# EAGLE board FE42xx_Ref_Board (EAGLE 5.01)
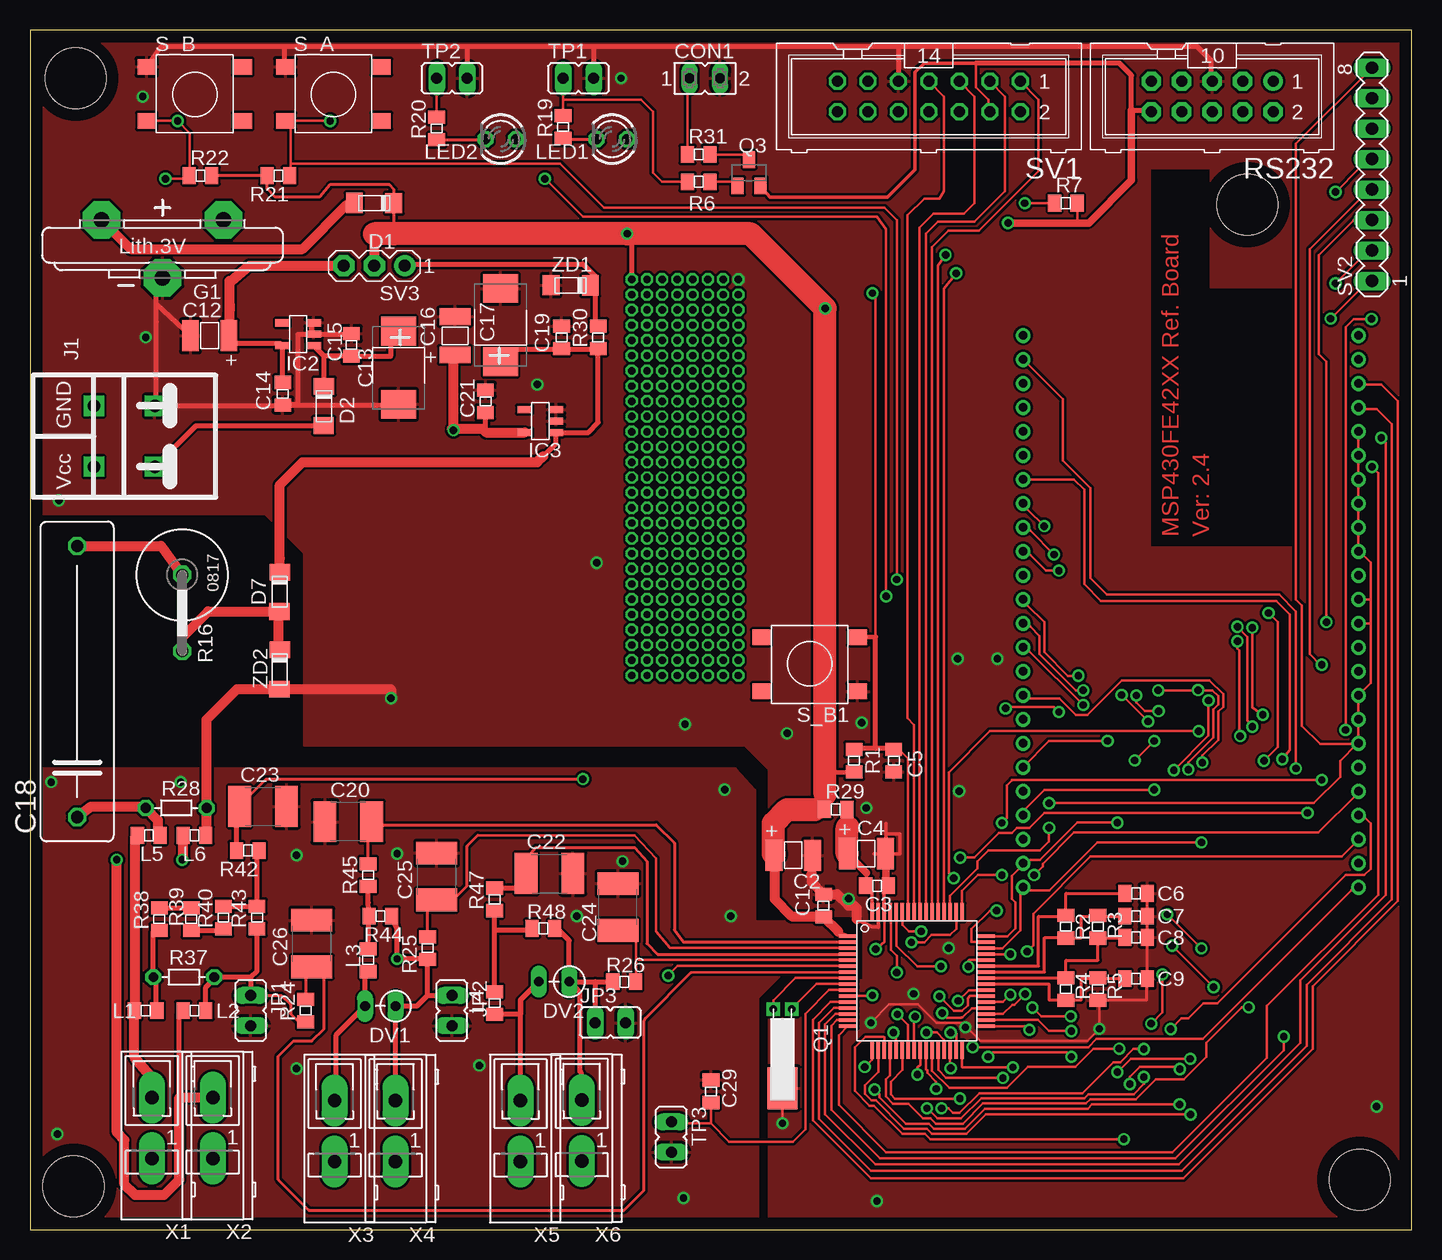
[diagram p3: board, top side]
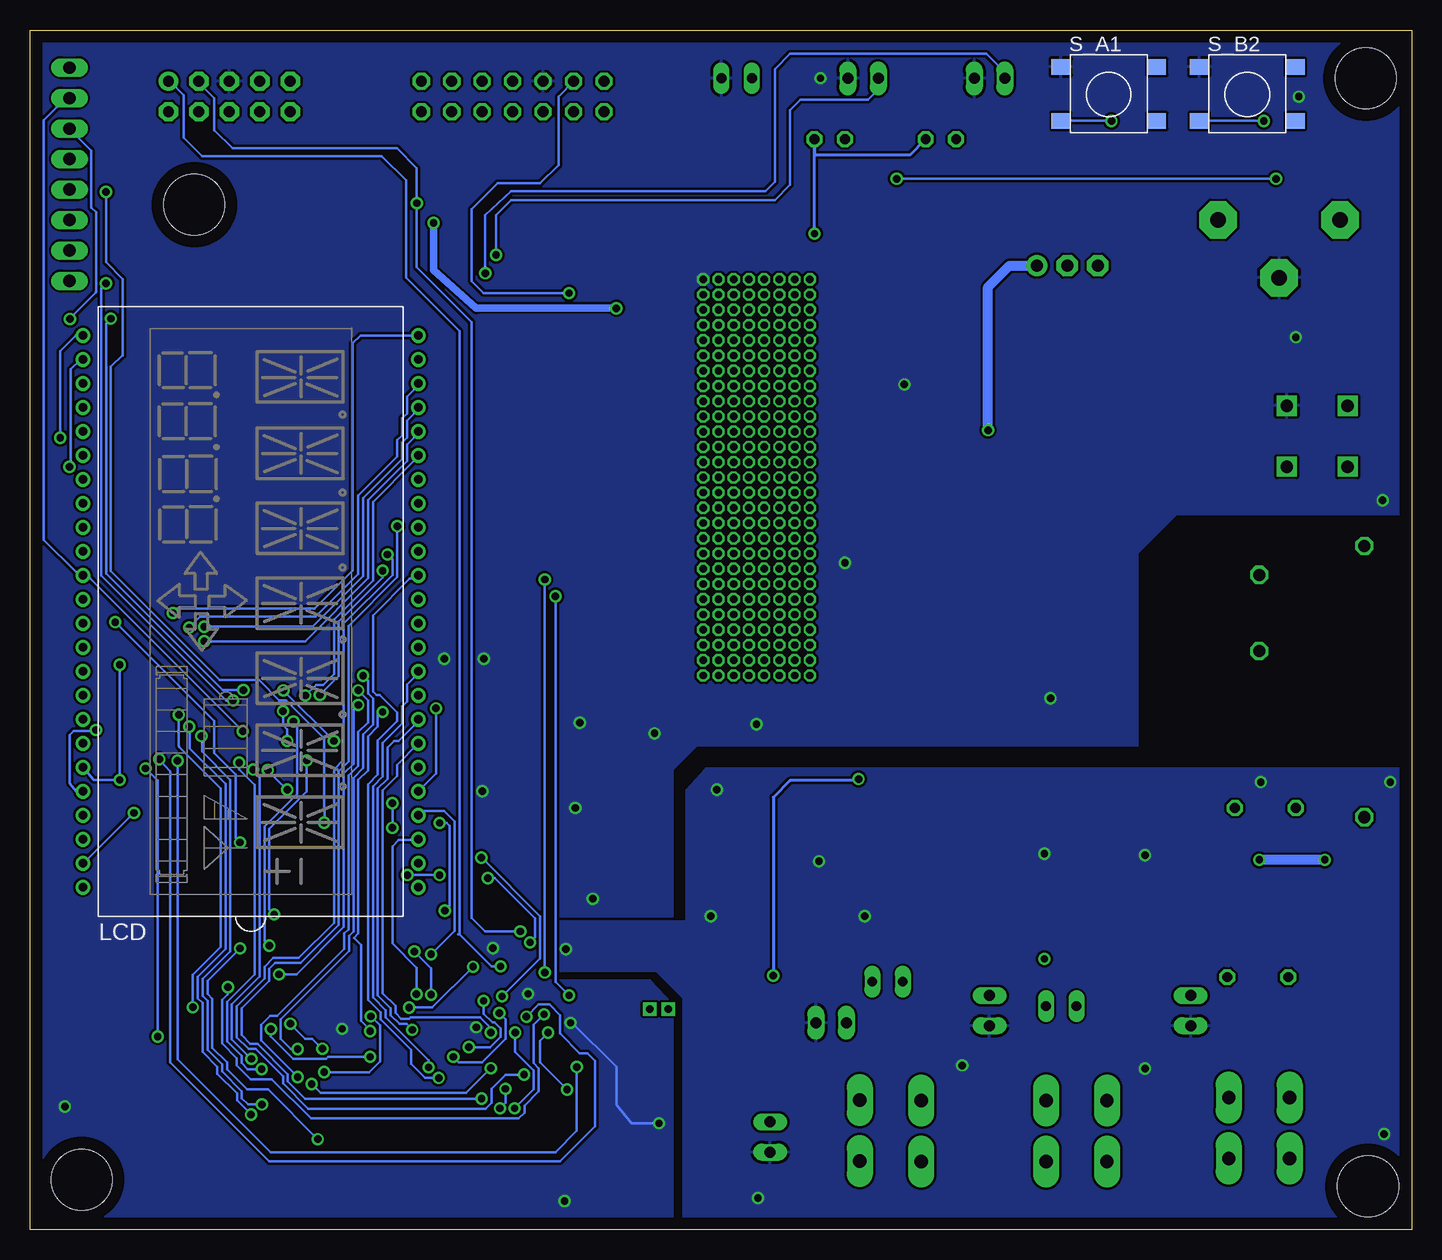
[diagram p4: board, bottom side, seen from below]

Size 115.17 x 100 mm. Coordinates in mm from the lower left corner, seen from the top.
Outline: 0,0 115.17,0 115.17,100 0,100 0,0
Copper layers (1*16): Top 0.035mm / dielectric 1.5mm / Bottom 0.035mm
Design rules "default": minimum track width 8mil, minimum drill 24mil, track to track 8mil, track to pad 8mil, pad to pad 6mil, via to via 8mil, smd to smd 8mil, copper to edge 40mil, drill to drill 8mil, minimum pad ring 10mil, minimum via ring 8mil, stop-mask expansion 4mil, vias tented up to drill 0mil, thermal gap 10mil
Holes 5.08 mm at 3.8,95.97 110.87,4.15 101.47,85.43 3.63,3.59
tRestrict: area 97.8,57 to 105.2,78.4; area 93.5,57 to 98.3,88.4

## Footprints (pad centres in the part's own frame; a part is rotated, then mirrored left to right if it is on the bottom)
CSMD0805 = smd 1.092 x 1.397: 1 -0.94,0; 2 0.94,0
1210ELKO = smd 1.397 x 2.591: + 1.6,0; - -1.6,0
7243 = smd 2.388 x 2.896: 1 -3.048,0; 2 3.048,0
0805 = smd 1.092 x 1.397: 1 -0.94,0; 2 0.94,0
C225-062X268 = drill 1.016 octagon: 1 -11.303,0; 2 11.303,0
C4532 = smd 1.9 x 3.4: 1 -1.95,0; 2 1.95,0
FE02-1 = drill 0.813 long: 1 -1.27,0; 2 1.27,0
SOD-80 = smd 1.397 x 1.702: 1 1.397,-0.025; 2 -1.88,0
RS-2,5 = drill 0.813 long: 1 -1.27,0; 2 1.27,0
CR2032V = drill 1.321 pad 3.15 octagon: + -2.54,-5.08; +@1 -2.54,5.08; - 2.286,0
SOT23/5 = smd 0.6 x 1.2: 1 -0.95,-1.306; 2 0,-1.306; 3 0.95,-1.306; 4 0.95,1.306; 5 -0.95,1.306
SUP_CON = drill 1.016 pad 1.676 square: GND1 2.54,2.54; GND2 2.54,-2.54; VCC1 -2.54,2.54; VCC2 -2.54,-2.54
JP1 = drill 0.914 long: 1 0,-1.27; 2 0,1.27
SBLCDA2 = drill 0.71 round: P$1 -23,-13.97; P$2 -21,-13.97; P$3 -19,-13.97; P$4 -17,-13.97; P$5 -15,-13.97; P$6 -13,-13.97; P$7 -11,-13.97; P$8 -9,-13.97; P$9 -7,-13.97; P$10 -5,-13.97; P$11 -3,-13.97; P$12 -1,-13.97; P$13 1,-13.97; P$14 3,-13.97; P$15 5,-13.97; P$16 7,-13.97; P$17 9,-13.97; P$18 11,-13.97; P$19 13,-13.97; P$20 15,-13.97; P$21 17,-13.97; P$22 19,-13.97; P$23 21,-13.97; P$24 23,-13.97; P$25 23,13.97; P$26 21,13.97; P$27 19,13.97; P$28 17,13.97; P$29 15,13.97; P$30 13,13.97; P$31 11,13.97; P$32 9,13.97; P$33 7,13.97; P$34 5,13.97; P$35 3,13.97; P$36 1,13.97; P$37 -1,13.97; P$38 -3,13.97; P$39 -5,13.97; P$40 -7,13.97; P$41 -9,13.97; P$42 -11,13.97; P$43 -13,13.97; P$44 -15,13.97; P$45 -17,13.97; P$46 -19,13.97; P$47 -21,13.97; P$48 -23,13.97
LED3MM = drill 0.813 octagon: A -1.27,0; K 1.27,0
QFP64PM = smd 1.5 x 0.3: 1 -0.75,8.75; 2 -0.75,8.25; 3 -0.75,7.75; 4 -0.75,7.25; 5 -0.75,6.75; 6 -0.75,6.25; 7 -0.75,5.75; 8 -0.75,5.25; 9 -0.75,4.75; 10 -0.75,4.25; 11 -0.75,3.75; 12 -0.75,3.25; 13 -0.75,2.75; 14 -0.75,2.25; 15 -0.75,1.75; 16 -0.75,1.25; 33 10.75,1.25; 34 10.75,1.75; 35 10.75,2.25; 36 10.75,2.75; 37 10.75,3.25; 38 10.75,3.75; 39 10.75,4.25; 40 10.75,4.75; 41 10.75,5.25; 42 10.75,5.75; 43 10.75,6.25; 44 10.75,6.75; 45 10.75,7.25; 46 10.75,7.75; 47 10.75,8.25; 48 10.75,8.75 | smd 0.3 x 1.5: 17 1.25,-0.75; 18 1.75,-0.75; 19 2.25,-0.75; 20 2.75,-0.75; 21 3.25,-0.75; 22 3.75,-0.75; 23 4.25,-0.75; 24 4.75,-0.75; 25 5.25,-0.75; 26 5.75,-0.75; 27 6.25,-0.75; 28 6.75,-0.75; 29 7.25,-0.75; 30 7.75,-0.75; 31 8.25,-0.75; 32 8.75,-0.75; 49 8.75,10.75; 50 8.25,10.75; 51 7.75,10.75; 52 7.25,10.75; 53 6.75,10.75; 54 6.25,10.75; 55 5.75,10.75; 56 5.25,10.75; 57 4.75,10.75; 58 4.25,10.75; 59 3.75,10.75; 60 3.25,10.75; 61 2.75,10.75; 62 2.25,10.75; 63 1.75,10.75; 64 1.25,10.75
QUARZ32K = drill 0.61 pad 1.016 square: 1 0,0.762; 2 0,-0.762 | smd 3.5 x 2.5: GND 6.604,0
SOT23-BEC = smd 1 x 1.4: B -0.95,-1.1; C 0,1.1; E 0.95,-1.1
P0817V = drill 1.016 octagon: 1 -5.08,0; 2 1.27,0
R-5 = drill 0.813 octagon: 1 -2.54,0; 2 2.54,0
ML10 = drill 0.914 pad 1.6 round: 1 -5.08,-1.27 | drill 0.914 pad 1.6 octagon: 2 -5.08,1.27; 3 -2.54,-1.27; 4 -2.54,1.27; 5 0,-1.27; 6 0,1.27; 7 2.54,-1.27; 8 2.54,1.27; 9 5.08,-1.27; 10 5.08,1.27
TASTER = smd 1.55 x 1.3: P$1 -0.8,0; P$2 7.2,0; TASTER1 -0.8,4.5; TASTER2 7.2,4.5
ML14 = drill 0.914 octagon: 1 -7.62,-1.27; 2 -7.62,1.27; 3 -5.08,-1.27; 4 -5.08,1.27; 5 -2.54,-1.27; 6 -2.54,1.27; 7 0,-1.27; 8 0,1.27; 9 2.54,-1.27; 10 2.54,1.27; 11 5.08,-1.27; 12 5.08,1.27; 13 7.62,-1.27; 14 7.62,1.27
MA08-1 = drill 1.016 long: 1 -8.89,0; 2 -6.35,0; 3 -3.81,0; 4 -1.27,0; 5 1.27,0; 6 3.81,0; 7 6.35,0; 8 8.89,0
MA03-1@2 = drill 1.016 pad 1.778 round: 1 -2.54,0 | drill 1.016 pad 1.778 octagon: 2 0,0; 3 2.54,0
W236-1 = drill 1.118 pad 2.184 long: 1 0,-2.54; 2 0,2.54

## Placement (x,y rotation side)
C1  100n  [CSMD0805]  66.16,27.01 90 top
C2  10u  [1210ELKO]  63.62,31.2 180 top
C3  100n  [CSMD0805]  70.61,28.66 0 top
C4  10u  [1210ELKO]  69.72,31.33 180 top
C5  10n  [CSMD0805]  72,39.08 270 top
C6  10n  [CSMD0805]  92.2,28.03 180 top
C7  10n  [CSMD0805]  92.2,26.12 180 top
C8  10n  [CSMD0805]  92.2,24.35 180 top
C9  n.a.(10n)  [CSMD0805]  92.2,20.92 180 top
C12  10u  [1210ELKO]  14.98,74.51 0 top
C13  10u  [7243]  30.73,71.84 90 top
C14  100n  [0805]  21.08,69.69 90 top
C15  100n  [0805]  26.79,73.75 270 top
C16  10u  [1210ELKO]  35.43,74.51 270 top
C17  220u/10V  [7243]  39.24,75.4 270 top
C18  470n / 200V~  [C225-062X268]  3.93,45.68 90 top
C19  100n  [CSMD0805]  44.32,74.38 270 top
C20  33n  [C4532]  26.54,34 180 top
C21  100n  [CSMD0805]  37.97,69.05 270 top
C22  33n  [C4532]  43.3,29.68 0 top
C23  33n  [C4532]  19.43,35.27 0 top
C24  33n  [C4532]  49.02,26.89 90 top
C25  33n  [C4532]  33.9,29.43 90 top
C26  33n  [C4532]  23.49,23.84 90 top
C29  100n  [0805]  56.76,11.52 270 top
CON1  FE02-1  [FE02-1]  56.26,95.97 0 top
D1  LL103A  [SOD-80]  28.44,85.56 180 top
D2  LL103A  [SOD-80]  24.51,68.41 270 top
D7  LL103A  [SOD-80]  20.82,52.92 270 top
DV1  5V  [RS-2,5]  29.2,18.63 180 top
DV2  5V  [RS-2,5]  43.68,20.66 180 top
G1  CR2032V  [CR2032V]  11.04,81.62 270 top
IC2  TPS77030  [SOT23/5]  22.35,74.64 90 top
IC3  TPS77030  [SOT23/5]  42.54,67.4 90 top
J1  SUP_CON  [SUP_CON]  7.87,66.13 90 top
JP1  [JP1]  18.41,18.25 180 top
JP2  [JP1]  35.17,18.25 180 top
JP3  [JP1]  48.38,17.23 270 top
L1  1uH  [0805]  9.65,18.25 0 top
L2  1uH  [0805]  13.71,18.25 0 top
L3  1uH  [0805]  28.19,22.44 90 top
L4  1uH  [0805]  38.73,18.88 90 top
L5  1uH  [0805]  9.9,32.85 0 top
L6  1uH  [0805]  13.71,32.85 0 top
LCD  SBLCDA2_DISPLAY  [SBLCDA2]  96.77,51.52 90 bottom
LED1  red 3mm  [LED3MM]  48.51,90.89 180 top
LED2  red 3mm  [LED3MM]  39.24,90.89 180 top
MSP1  [QFP64PM]  68.96,15.71 0 top
Q1  32kHz  [QUARZ32K]  62.73,18.38 270 top
Q3  BC807-16SMD  [SOT23-BEC]  59.94,88.1 0 top
R1  47k  [0805]  68.7,39.08 90 top
R2  820k  [0805]  86.35,25.23 270 top
R3  820k  [0805]  89.02,25.23 270 top
R4  820k  [0805]  86.35,20.03 270 top
R5  0  [0805]  89.02,20.03 270 top
R6  10k  [0805]  55.75,87.34 0 top
R7  470k  [0805]  86.35,85.56 0 top
R16  560R / 5W  [P0817V]  12.7,49.49 270 top
R19  820  [0805]  44.45,91.91 90 top
R20  820  [0805]  33.9,91.78 90 top
R21  100k  [0805]  20.7,87.85 180 top
R22  100k  [0805]  14.22,87.85 0 top
R24  1k  [0805]  22.98,18.25 90 top
R25  1k  [0805]  33.14,23.46 90 top
R26  1k  [0805]  49.53,20.66 0 top
R28  275V  [R-5]  12.19,35.14 0 top
R29  10R  [0805]  67.18,35.01 0 top
R30  opt.  [0805]  47.37,74.38 90 top
R31  82R  [0805]  55.75,89.62 0 top
R37  275V  [R-5]  12.82,21.04 0 top
R38  330k  [0805]  10.79,25.87 90 top
R39  330k  [0805]  13.46,25.87 270 top
R40  330k  [0805]  16.12,26 90 top
R42  1k  [0805]  18.16,31.58 180 top
R43  1k5  [0805]  18.92,26 90 top
R44  -  [0805]  29.2,26.12 180 top
R45  1k  [0805]  28.19,29.55 90 top
R47  1k  [0805]  38.73,27.52 90 top
R48  -  [0805]  42.79,25.11 180 top
RS232  ML10  [ML10]  98.55,94.45 180 top
S_A  TASTER  [TASTER]  22.09,92.42 0 top
S_A1  TASTER  [TASTER]  28.44,92.42 0 bottom
S_B  TASTER  [TASTER]  10.54,92.42 0 top
S_B1  TASTER  [TASTER]  68.19,49.37 180 top
S_B2  TASTER  [TASTER]  16.89,92.42 0 bottom
SV1  JTAG  [ML14]  74.92,94.45 180 top
SV2  [MA08-1]  111.88,87.97 90 top
SV3  VCC select  [MA03-1@2]  28.7,80.35 180 top
TP1  [JP1]  45.72,95.97 270 top
TP2  [JP1]  35.17,95.97 270 top
TP3  [JP1]  53.46,7.71 180 top
X1  W236-1  [W236-1]  10.16,8.47 180 top
X2  W236-1  [W236-1]  15.24,8.47 180 top
X3  W236-1  [W236-1]  25.39,8.22 180 top
X4  W236-1  [W236-1]  30.47,8.22 180 top
X5  W236-1  [W236-1]  40.89,8.22 180 top
X6  W236-1  [W236-1]  45.99,8.24 180 top
ZD1  (opt) 3.3V  [SOD-80]  44.83,78.7 180 top
ZD2  3.9V  [SOD-80]  20.82,46.44 270 top

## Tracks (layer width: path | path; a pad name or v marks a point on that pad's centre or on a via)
AVCC
  Top 0.305: 69.72,29.73 69.72,28.71 C3.1 70.2,28.08 70.2,27.09 MSP1.64
  Top 0.406: 68.12,33.49 R29.2
  Top 0.61: C4.+ 68.19,31.33 68.19,31.25 69.72,29.73
  Top 1.93: C4.+ 68.12,33.49 68.19,33.49
AVSS  (via drill 0.61)
  Top 0.203: v70.5,23.38 71.24,23.96 71.24,26.38 71.21,26.41 MSP1.62
  Top 0.305: 71.32,28.97 71.62,28.66 C3.2 71.5,28.66 71.21,28.37 MSP1.62
  Top 0.61: C4.- 71.37,31.33 71.37,29.02 71.32,28.97
  other vias: 1.77,37.3 2.28,7.96 54.48,2.63 37.46,13.68 12.57,37.3 22.22,31.2 30.6,31.33 49.4,30.7 22.22,13.42 45.59,26.12 57.91,36.66 58.41,26.12
  pour Bottom: 0.76,0.6 0.76,38.44 58.8,38.44 60.45,36.66 60.45,25.69 71.98,25.69 71.98,21.55 62.99,21.55 60.7,19.27 60.7,0.6
  pour Top: 60.7,0.6 60.7,19.27 62.99,21.55 68.88,21.55 68.88,25.67 60.45,25.67 60.45,36.66 58.8,38.44 0.76,38.44 0.76,0.6
COM0  (via drill 0.61)
  Top 0.203: v76.04,18.05 76.42,17.67 77.62,17.67 77.64,17.69 77.74,17.69 78.51,18.45 78.96,18.45 MSP1.36 | v79.88,14.39 80.26,14.77 86.43,14.77 v86.81,14.39 | v95.09,16.7 95.98,17.59 96.57,17.59 97.81,18.83 98.98,18.83 109.7,29.55 111.25,29.55 111.75,30.06 111.75,33.87 111.12,34.51 110.74,34.51 LCD.P$45
  Bottom 0.203: v76.04,18.05 75.53,17.54 75.53,15.89 77.46,13.96 79.45,13.96 v79.88,14.39 | v86.81,14.39 90.32,14.39 90.47,14.24 93.21,14.24 95.09,16.12 v95.09,16.7
COM1  (via drill 0.61)
  Top 0.203: v81.73,19.57 81.12,18.96 80.44,18.96 MSP1.37 | v83.13,23.18 83.64,23.69 83.64,26.33 88.41,31.1 109.37,31.1 110.74,32.47 LCD.P$46
  Bottom 0.203: v81.73,19.57 81.73,21.78 v83.13,23.18
COM2  (via drill 0.61)
  Top 0.203: v75.81,19.44 77.03,18.22 77.69,18.22 78.18,18.71 78.18,19.29 78.35,19.47 78.96,19.47 MSP1.38 | v77.54,31 78.71,31 80.77,33.06 81.86,33.06 82.29,33.49 83.31,33.49 84.55,34.73 v106.5,34.73
  Bottom 0.203: v75.81,19.44 72.66,22.59 72.66,26.12 v77.54,31 | v106.5,34.73 106.52,34.73 110.66,30.59 LCD.P$47
COM3  (via drill 0.61)
  Top 0.203: v77.36,19.06 78.25,19.95 78.96,19.95 MSP1.39 | v78.58,15.2 88.21,15.2 88.89,15.89 97.78,15.89 110.16,28.26 LCD.P$48
  Bottom 0.203: v77.36,19.06 77.36,18 76.63,17.26 76.42,17.26 75.94,16.78 75.94,16.07 76.8,15.2 v78.58,15.2
GND  (via drill 0.61)
  Top 0.203: 21.2,96.86 21.24,96.86 S_A.TASTER1 21.29,98.64 | v70.1,17.23 71.62,18.76 74.04,18.76 75.56,17.23 77.72,17.23 78.1,16.85 | 78.1,16.85 v77.97,16.85 | 78.1,16.85 79.24,15.71 88.13,15.71 v89.15,16.73 89.15,19.01 89.02,19.14 | v62.73,8.85 Q1.GND
  Top 0.254: R5.2 89.02,19.14 93.09,19.14 93.09,20.92 C9.1 C8.1 | C8.1 93.21,24.35 | C8.1 C7.1 | C7.1 93.09,26.12 | C7.1 C6.1 93.09,28.03
  Top 0.305: MSP1.63 70.71,25.19 70.71,25.23 70.17,25.23 68.91,25.87 | 71.37,32.98 71.37,33.87 | 70.35,31.33 72.51,31.33 72.51,32.98 71.37,32.98 | 71.37,32.98 71.37,32.47
  Top 0.406: S_B.TASTER1 10.95,98.64 21.2,98.64 21.2,96.86 | 21.29,98.64 36.44,98.64 | 36.44,98.64 TP2.2 | 36.44,98.64 46.98,98.64 | 46.98,98.64 TP1.2 | 46.98,98.64 72.38,98.64 | 72.38,98.64 SV1.9 | 43.81,68.39 IC3.3 43.81,68.31 | 10.54,75.65 10.54,68.03 J1.GND2 20.82,68.67 20.95,68.8 20.82,68.8 20.95,68.67 21.03,68.75 C14.1 | C13.1 30.6,68.8 30.55,68.75 C14.1 | IC2.2 22.35,74.64 22.35,68.8 21.08,68.8 C14.1 | IC2.2 23.49,74.64 23.49,75.59 IC2.3 | C15.1 26.66,74.69 26.66,74.64 IC2.2 | 65.15,29.68 65.15,29.43 65.22,29.43 C2.- | L6.2 14.73,32.93 | C12.- 10.54,77.18 10.54,75.65 | 10.54,75.65 10.54,80.1 G1.- | 72.38,98.64 97.28,98.64 98.42,97.5 98.42,95.72 98.55,95.59 RS232.5
  Top 0.813: 68.91,25.87 68.91,26.81 68.7,27.01 68.22,27.01 67.28,27.95 C1.2 65.2,28.92 65.15,29.68 | 14.73,32.93 R28.2 14.73,42.51 17.27,45.05 20.82,45.05 | 20.82,45.05 20.54,45.07 ZD2.1 20.82,45.05 | 20.82,45.05 30.09,45.05 v30.09,44.28
  Bottom 0.203: v70.1,17.23 69.97,17.23 66.29,13.55 66.29,10.38 65.02,8.85 62.61,8.85 62.73,8.98 v62.73,8.85
  other vias: 42.29,70.45 73.66,19.65 68.24,27.57 69.34,42.25 70.61,2.38 49.27,95.97 9.39,94.45 2.41,60.8 54.61,42.13 63.11,41.36 77.34,47.59 69.72,35.14 9.65,74.38 47.24,55.59 112.26,10.25 76.58,23.46 59.05,79.21 80.64,47.59 77.46,36.54
  pour Bottom: 0.76,99.66 114.55,99.91 114.55,0.6 61.59,0.6 61.59,18.76 63.5,20.79 72.64,20.79 72.64,26.12 61.59,26.12 61.59,38.32 59.56,40.35 22.86,40.35 22.86,56.35 19.55,59.65 0.76,59.65
  pour Top: 0.76,99.66 114.55,99.66 114.55,0.6 61.59,0.6 61.59,18.76 63.5,20.79 69.49,20.79 69.49,26.15 61.59,26.12 61.59,38.32 59.56,40.35 22.86,40.35 22.86,56.35 19.55,59.65 0.76,59.65
I1+
  Top 0.254: MSP1.2 54.47,23.96 53.72,24.98 53.72,32.22 52.19,33.74 28.82,33.74 28.57,34 C20.1 28.19,33.32 R45.2
I1-
  Top 0.203: MSP1.3 53.34,23.46 52.19,24.85 52.19,30.95 50.41,32.85 37.33,32.85
  Top 0.254: 37.33,32.85 36.44,31.97 36.44,28.66 35.43,27.65 33.9,27.65 C25.1 33.14,26.71 R25.2 33.14,24.35
I2+
  Top 0.254: MSP1.4 68.19,22.95 52.32,22.95 51.43,23.84 51.43,30.7 50.41,31.84 42.16,31.84 41.4,30.95 | 41.32,28.49 41.35,29.63 41.4,30.95 | 41.4,30.95 C22.1
  Top 0.406: R47.2 41.27,28.46 41.27,28.28 41.32,28.49
I2-
  Top 0.203: 50.54,22.57 50.67,22.57 50.78,22.46 MSP1.5 | C24.1 48.38,24.85 50.54,24.85 50.54,22.57 | R26.2 50.59,20.87 50.54,20.92 50.54,22.57
IS1+
  Top 0.406: 25.27,12.41 X3.1 25.39,12.41 25.52,12.41 25.52,16.22 DV1.2 27.93,21.3 28.19,21.3 L3.1
IS2+
  Top 0.406: X5.1 40.89,19.14 | 40.89,19.14 DV2.2 | L4.1 40.89,17.95 40.89,19.14
N$1
  Top 0.203: Q3.B 58.97,87.25 59.05,87.34 R6.2
N$2  (via drill 0.61)
  other vias: 50.16,77.94
N$3
  Top 0.406: R48.2 41.78,24.98 38.73,24.98 | 38.73,24.98 R47.1 | L4.2 38.73,24.98
N$4  (via drill 0.61)
  other vias: 50.16,76.67
N$5
  Top 0.813: R16.2 12.7,49.37 14.85,51.52 D7.1 20.7,50.76 20.7,48.48 20.57,48.35 ZD2.2
N$6
  Top 0.254: 14.98,20.54 R37.2 | R24.1 22.4,17.31 21.71,18 21.71,18.76 20.95,19.52 JP1.1
  Top 0.406: R43.1 18.92,21.55 18.41,21.04 | R37.2 18.41,21.04 | L2.2 14.65,20.21 14.98,20.54 | 18.41,21.04 JP1.1
N$7  (via drill 0.61)
  other vias: 50.16,75.4
N$8
  Top 0.406: R45.1 28.19,27.27 R44.2 L3.2
N$9  (via drill 0.61)
  other vias: 50.16,74.13
N$10
  Top 0.813: C18.2 10.92,56.98 R16.1
N$11  (via drill 0.61)
  other vias: 50.16,71.59
N$12  (via drill 0.61)
  other vias: 50.16,72.86
N$13  (via drill 0.61)
  other vias: 50.16,70.32
N$14  (via drill 0.61)
  other vias: 50.16,69.05
N$15  (via drill 0.61)
  other vias: 50.16,67.78
N$16  (via drill 0.61)
  other vias: 50.16,66.51
N$17
  Top 0.254: 44.57,90.97 44.57,91.02 | R19.1 44.57,90.97 | LED1.K 44.57,90.89 44.57,90.97
N$18
  Top 0.254: R20.1 37.97,90.84 LED2.K
N$19  (via drill 0.61)
  other vias: 50.16,65.24
N$20  (via drill 0.61)
  other vias: 50.16,63.97
N$21  (via drill 0.61)
  other vias: 50.16,62.7
N$22  (via drill 0.61)
  other vias: 50.16,61.43
N$23  (via drill 0.61)
  other vias: 50.16,60.16
N$24  (via drill 0.61)
  other vias: 50.16,58.89
N$25  (via drill 0.61)
  other vias: 50.16,57.62
N$26  (via drill 0.61)
  other vias: 50.16,56.35
N$27  (via drill 0.61)
  other vias: 50.16,55.08
N$28  (via drill 0.61)
  other vias: 50.16,53.81
N$29  (via drill 0.61)
  other vias: 50.16,52.54
N$30  (via drill 0.61)
  other vias: 50.16,51.27
N$31  (via drill 0.61)
  other vias: 50.16,50
N$32  (via drill 0.61)
  other vias: 50.16,48.73
N$33
  Top 0.406: 13.51,26.81 R39.1 | R38.2 13.51,26.81 | 13.51,26.81 13.58,26.89
N$34  (via drill 0.61)
  other vias: 50.16,47.46
N$35
  Top 0.406: 26.84,72.86 26.92,72.86 | 26.84,72.86 C15.2 30.04,72.81 30.09,72.86 30.09,74.26 C13.2 30.6,75.02 | IC2.1 24.48,72.86 24.51,72.86 | 24.51,72.86 26.84,72.86 | D2.2 24.51,72.86
N$36  (via drill 0.61)
  other vias: 50.16,46.19
N$37  (via drill 0.61)
  other vias: 51.43,79.21
N$38  (via drill 0.61)
  other vias: 51.43,77.94
N$39  (via drill 0.61)
  other vias: 51.43,76.67
N$40  (via drill 0.61)
  other vias: 51.43,75.4
N$41  (via drill 0.61)
  other vias: 51.43,74.13
N$42  (via drill 0.61)
  other vias: 51.43,71.59
N$43  (via drill 0.61)
  other vias: 51.43,72.86
N$44  (via drill 0.61)
  other vias: 51.43,70.32
N$45
  Top 0.406: R40.1 16.12,24.98 16.2,24.93 R39.2
N$46
  Top 0.406: R43.2 19.04,26.89 18.99,26.94 R43.2 | R40.2 R43.2 | R42.1 18.92,31.58 R43.2
N$47  (via drill 0.61)
  other vias: 51.43,69.05
N$48
  Top 0.406: 26.41,85.43 26.54,85.43 D1.1
  Top 0.813: G1.+ 8.38,81.75 22.73,81.75 26.41,85.43
N$49  (via drill 0.61)
  other vias: 51.43,67.78
N$50  (via drill 0.61)
  other vias: 51.43,66.51
N$51  (via drill 0.61)
  other vias: 51.43,65.24
N$52  (via drill 0.61)
  other vias: 51.43,63.97
N$53  (via drill 0.61)
  other vias: 51.43,62.7
N$54  (via drill 0.61)
  other vias: 51.43,61.43
N$55  (via drill 0.61)
  other vias: 51.43,60.16
N$56  (via drill 0.61)
  other vias: 51.43,58.89
N$57  (via drill 0.61)
  other vias: 51.43,57.62
N$58  (via drill 0.61)
  other vias: 51.43,56.35
N$59  (via drill 0.61)
  other vias: 51.43,55.08
N$60  (via drill 0.61)
  other vias: 51.43,53.81
N$61  (via drill 0.61)
  other vias: 51.43,52.54
N$62  (via drill 0.61)
  other vias: 51.43,51.27
N$63  (via drill 0.61)
  other vias: 51.43,50
N$64  (via drill 0.61)
  other vias: 51.43,48.73
N$65  (via drill 0.61)
  other vias: 51.43,47.46
N$66  (via drill 0.61)
  other vias: 51.43,46.19
N$67  (via drill 0.61)
  other vias: 52.7,79.21
N$68  (via drill 0.61)
  other vias: 52.7,77.94
N$69  (via drill 0.61)
  other vias: 52.7,76.67
N$70  (via drill 0.61)
  other vias: 52.7,75.4
N$71  (via drill 0.61)
  other vias: 52.7,74.13
N$72  (via drill 0.61)
  other vias: 52.7,71.59
N$73  (via drill 0.61)
  other vias: 52.7,72.86
N$74  (via drill 0.61)
  other vias: 52.7,70.32
N$75  (via drill 0.61)
  other vias: 52.7,69.05
N$76  (via drill 0.61)
  other vias: 52.7,67.78
N$77  (via drill 0.61)
  other vias: 52.7,66.51
N$78  (via drill 0.61)
  other vias: 52.7,65.24
N$79  (via drill 0.61)
  other vias: 52.7,63.97
N$80  (via drill 0.61)
  other vias: 52.7,62.7
N$81  (via drill 0.61)
  other vias: 52.7,61.43
N$82  (via drill 0.61)
  other vias: 52.7,60.16
N$83  (via drill 0.61)
  other vias: 52.7,58.89
N$84  (via drill 0.61)
  other vias: 52.7,57.62
N$85  (via drill 0.61)
  other vias: 52.7,56.35
N$86  (via drill 0.61)
  other vias: 52.7,55.08
N$87  (via drill 0.61)
  other vias: 52.7,53.81
N$88  (via drill 0.61)
  other vias: 52.7,52.54
N$89  (via drill 0.61)
  other vias: 52.7,51.27
N$90  (via drill 0.61)
  other vias: 52.7,50
N$91  (via drill 0.61)
  other vias: 52.7,48.73
N$92  (via drill 0.61)
  other vias: 52.7,47.46
N$93  (via drill 0.61)
  other vias: 52.7,46.19
N$94  (via drill 0.61)
  other vias: 53.97,79.21
N$95  (via drill 0.61)
  other vias: 53.97,77.94
N$96  (via drill 0.61)
  other vias: 53.97,76.67
N$97  (via drill 0.61)
  other vias: 53.97,75.4
N$98  (via drill 0.61)
  other vias: 53.97,74.13
N$99  (via drill 0.61)
  other vias: 53.97,71.59
N$100  (via drill 0.61)
  other vias: 53.97,72.86
N$101  (via drill 0.61)
  other vias: 53.97,70.32
N$102  (via drill 0.61)
  other vias: 53.97,69.05
N$103  (via drill 0.61)
  other vias: 53.97,67.78
N$104  (via drill 0.61)
  other vias: 53.97,66.51
N$105  (via drill 0.61)
  other vias: 53.97,65.24
N$106  (via drill 0.61)
  other vias: 53.97,63.97
N$107  (via drill 0.61)
  other vias: 53.97,62.7
N$108  (via drill 0.61)
  other vias: 53.97,61.43
N$109  (via drill 0.61)
  other vias: 53.97,60.16
N$110  (via drill 0.61)
  other vias: 53.97,58.89
N$111  (via drill 0.61)
  other vias: 53.97,57.62
N$112  (via drill 0.61)
  other vias: 53.97,56.35
N$113  (via drill 0.61)
  other vias: 53.97,55.08
N$114  (via drill 0.61)
  other vias: 53.97,53.81
N$115  (via drill 0.61)
  other vias: 53.97,52.54
N$116  (via drill 0.61)
  other vias: 53.97,51.27
N$117  (via drill 0.61)
  other vias: 53.97,50
N$118  (via drill 0.61)
  other vias: 53.97,48.73
N$119  (via drill 0.61)
  other vias: 53.97,47.46
N$120  (via drill 0.61)
  other vias: 53.97,46.19
N$121  (via drill 0.61)
  other vias: 55.24,79.21
N$122  (via drill 0.61)
  other vias: 55.24,77.94
N$123  (via drill 0.61)
  other vias: 55.24,76.67
N$124  (via drill 0.61)
  other vias: 55.24,75.4
N$125  (via drill 0.61)
  other vias: 55.24,74.13
N$126  (via drill 0.61)
  other vias: 55.24,71.59
N$127  (via drill 0.61)
  other vias: 55.24,72.86
N$128  (via drill 0.61)
  other vias: 55.24,70.32
N$129  (via drill 0.61)
  other vias: 55.24,69.05
N$130  (via drill 0.61)
  other vias: 55.24,67.78
N$131  (via drill 0.61)
  other vias: 55.24,66.51
N$132  (via drill 0.61)
  other vias: 55.24,65.24
N$133  (via drill 0.61)
  other vias: 55.24,63.97
N$134  (via drill 0.61)
  other vias: 55.24,62.7
N$135  (via drill 0.61)
  other vias: 55.24,61.43
N$136  (via drill 0.61)
  other vias: 55.24,60.16
N$137  (via drill 0.61)
  other vias: 55.24,58.89
N$138  (via drill 0.61)
  other vias: 55.24,57.62
N$139  (via drill 0.61)
  other vias: 55.24,56.35
N$140  (via drill 0.61)
  other vias: 55.24,55.08
N$141  (via drill 0.61)
  other vias: 55.24,53.81
N$142  (via drill 0.61)
  other vias: 55.24,52.54
N$143  (via drill 0.61)
  other vias: 55.24,51.27
N$144  (via drill 0.61)
  other vias: 55.24,50
N$145  (via drill 0.61)
  other vias: 55.24,48.73
N$146  (via drill 0.61)
  other vias: 55.24,47.46
N$147  (via drill 0.61)
  other vias: 55.24,46.19
N$148  (via drill 0.61)
  other vias: 56.51,79.21
N$149  (via drill 0.61)
  other vias: 56.51,77.94
N$150  (via drill 0.61)
  other vias: 56.51,76.67
N$151  (via drill 0.61)
  other vias: 56.51,75.4
N$152  (via drill 0.61)
  other vias: 56.51,74.13
N$153  (via drill 0.61)
  other vias: 56.51,71.59
N$154  (via drill 0.61)
  other vias: 56.51,72.86
N$155  (via drill 0.61)
  other vias: 56.51,70.32
N$156  (via drill 0.61)
  other vias: 56.51,69.05
N$157  (via drill 0.61)
  other vias: 56.51,67.78
N$158  (via drill 0.61)
  other vias: 56.51,66.51
N$159  (via drill 0.61)
  other vias: 56.51,65.24
N$160  (via drill 0.61)
  other vias: 56.51,63.97
N$161  (via drill 0.61)
  other vias: 56.51,62.7
N$162  (via drill 0.61)
  other vias: 56.51,61.43
N$163  (via drill 0.61)
  other vias: 56.51,60.16
N$164  (via drill 0.61)
  other vias: 56.51,58.89
N$165  (via drill 0.61)
  other vias: 56.51,57.62
N$166  (via drill 0.61)
  other vias: 56.51,56.35
N$167  (via drill 0.61)
  other vias: 56.51,55.08
N$168  (via drill 0.61)
  other vias: 56.51,53.81
N$169  (via drill 0.61)
  other vias: 56.51,52.54
N$170  (via drill 0.61)
  other vias: 56.51,51.27
N$171  (via drill 0.61)
  other vias: 56.51,50
N$172  (via drill 0.61)
  other vias: 56.51,48.73
N$173  (via drill 0.61)
  other vias: 56.51,47.46
N$174  (via drill 0.61)
  other vias: 56.51,46.19
N$175  (via drill 0.61)
  other vias: 57.78,79.21
N$176  (via drill 0.61)
  other vias: 57.78,77.94
N$177  (via drill 0.61)
  other vias: 57.78,76.67
N$178  (via drill 0.61)
  other vias: 57.78,75.4
N$179  (via drill 0.61)
  other vias: 57.78,74.13
N$180  (via drill 0.61)
  other vias: 57.78,71.59
N$181  (via drill 0.61)
  other vias: 57.78,72.86
N$182  (via drill 0.61)
  other vias: 57.78,70.32
N$183  (via drill 0.61)
  other vias: 57.78,69.05
N$184  (via drill 0.61)
  other vias: 57.78,67.78
N$185  (via drill 0.61)
  other vias: 57.78,66.51
N$186  (via drill 0.61)
  other vias: 57.78,65.24
N$187  (via drill 0.61)
  other vias: 57.78,63.97
N$188  (via drill 0.61)
  other vias: 57.78,62.7
N$189  (via drill 0.61)
  other vias: 57.78,61.43
N$190  (via drill 0.61)
  other vias: 57.78,60.16
N$191  (via drill 0.61)
  other vias: 57.78,58.89
N$192  (via drill 0.61)
  other vias: 57.78,57.62
N$193  (via drill 0.61)
  other vias: 57.78,56.35
N$194  (via drill 0.61)
  other vias: 57.78,55.08
N$195  (via drill 0.61)
  other vias: 57.78,53.81
N$196  (via drill 0.61)
  other vias: 57.78,52.54
N$197  (via drill 0.61)
  other vias: 57.78,51.27
N$198  (via drill 0.61)
  other vias: 57.78,50
N$199  (via drill 0.61)
  other vias: 57.78,48.73
N$200  (via drill 0.61)
  other vias: 57.78,47.46
N$201  (via drill 0.61)
  other vias: 57.78,46.19
N$202  (via drill 0.61)
  Top 0.406: 33.14,19.52 R25.1 33.14,22.57 v30.6,22.57 30.6,25.11 R44.1 | 33.14,19.52 32.25,18.63 DV1.1 X4.1 | 33.14,19.52 JP2.1
N$203  (via drill 0.61)
  other vias: 59.05,77.94
N$204  (via drill 0.61)
  other vias: 59.05,76.67
N$205  (via drill 0.61)
  other vias: 59.05,75.4
N$206  (via drill 0.61)
  other vias: 59.05,74.13
N$207  (via drill 0.61)
  other vias: 59.05,71.59
N$208  (via drill 0.61)
  other vias: 59.05,72.86
N$209  (via drill 0.61)
  other vias: 59.05,70.32
N$210  (via drill 0.61)
  other vias: 59.05,69.05
N$211  (via drill 0.61)
  other vias: 59.05,67.78
N$212  (via drill 0.61)
  other vias: 59.05,66.51
N$213  (via drill 0.61)
  other vias: 59.05,65.24
N$214  (via drill 0.61)
  other vias: 59.05,63.97
N$215  (via drill 0.61)
  other vias: 59.05,62.7
N$216  (via drill 0.61)
  other vias: 59.05,61.43
N$217  (via drill 0.61)
  other vias: 59.05,60.16
N$218  (via drill 0.61)
  other vias: 59.05,58.89
N$219  (via drill 0.61)
  other vias: 59.05,57.62
N$220  (via drill 0.61)
  other vias: 59.05,56.35
N$221  (via drill 0.61)
  other vias: 59.05,55.08
N$222  (via drill 0.61)
  other vias: 59.05,53.81
N$223  (via drill 0.61)
  other vias: 59.05,52.54
N$224  (via drill 0.61)
  other vias: 59.05,51.27
N$225  (via drill 0.61)
  other vias: 59.05,50
N$226  (via drill 0.61)
  other vias: 59.05,48.73
N$227  (via drill 0.61)
  other vias: 59.05,47.46
N$228  (via drill 0.61)
  other vias: 59.05,46.19
N$229
  Top 0.406: R48.1 43.73,25.03 43.68,24.98 44.06,24.98 44.95,24.09 DV2.1 | X6.1 45.97,13.04 45.84,13.17 45.84,19.77 DV2.1 | 48.64,20.66 R26.1 47.11,20.66 | DV2.1 47.11,20.66 | 47.11,20.66 JP3.1
N$453
  Top 0.203: 54.81,90.97 R31.1 54.81,95.67 55.11,95.97 CON1.1
N$454
  Top 0.203: Q3.C 59.9,89.29 59.56,89.62 R31.2
P1+
  Top 0.406: X1.1 10.28,12.54 | L1.1 8.76,18.25 | 8.76,32.65 L5.1
  Top 0.813: L1.1 8.71,14.36 10.28,12.54 | 8.76,18.25 8.76,32.65
P1+1
  Top 0.406: R38.1 10.28,24.85 R37.1 10.54,20.79 10.54,18.25 L1.2
P1+2
  Top 0.406: 10.66,32.85 L5.2
  Top 0.813: 10.66,32.85 10.66,34.12 R28.1 9.52,35.27 5.08,35.27 C18.1
P1-  (via drill 0.61)
  Top 0.406: L2.1 12.77,18.17 12.44,18 12.44,11.01 | v12.7,30.82 12.77,30.9
  Top 0.813: X2.1 12.44,11.01 12.44,4.15 11.17,2.88 8.76,2.88 7.87,3.77 7.87,7.46 7.23,8.09 v7.23,30.82 | 12.77,30.9 L6.1
  Bottom 0.813: v7.23,30.82 v12.7,30.82
P1.0  (via drill 0.61)
  Top 0.203: MSP1.53 75.71,80.37 v76.32,81.24 | TP1.1 44.45,94.2 | 44.45,94.2 R19.2 44.45,92.8 | R6.1 52.7,87.34 51.94,88.1 51.94,93.18 50.92,94.2 44.45,94.2
  Bottom 0.203: v76.32,81.24 76.32,84.54 75.05,85.81 53.08,85.81 51.81,87.08 51.81,93.31 50.92,94.2 45.33,94.2 44.57,94.96 44.57,95.97 TP1.1
P1.1  (via drill 0.61)
  Top 0.203: MSP1.52 76.19,26.47 76.19,78.45 v77.21,79.72 | TP2.1 R20.2
  Bottom 0.203: v77.21,79.72 77.21,84.54 75.05,86.58 53.84,86.58 53.08,87.34 53.08,96.74 51.81,98.01 35.43,98.01 33.9,96.48 TP2.1
P2.2  (via drill 0.61)
  Top 0.203: MSP1.11 70.17,19.46 v70.23,19.52 | v71.37,52.79 71.37,83.4 70.61,84.42 46.1,84.42 v42.92,87.59 | S_B.P$1 v12.31,92.42 13.33,91.4 13.33,87.85 | 13.33,87.85 R22.1 | v11.3,87.59 13.33,87.59 13.33,87.85
  Bottom 0.203: v70.23,19.52 71.37,20.66 v71.37,52.79 | v42.92,87.59 v11.3,87.59 | 17.77,92.42 S_B2.P$1 v12.31,92.42
P2.3  (via drill 0.61)
  Top 0.203: v72.26,54.19 72.26,84.16 71.24,85.18 47.87,85.18 44.19,88.86 21.71,88.86 21.71,87.85 | v72.26,21.42 72.26,22.82 71.75,23.33 71.75,26.42 MSP1.61 | 21.71,87.85 R21.1 | 21.71,92.42 S_A.P$1 | 21.71,87.85 21.71,92.42 | 21.71,92.42 v25.01,92.42
  Bottom 0.203: v72.26,21.42 v72.26,54.19 | v25.01,92.42 S_A1.P$1
P2.4  (via drill 0.61)
  Top 0.203: MSP1.60 72.2,26.35 72.23,26.15 72.23,23.66 73.96,21.93 v75.94,21.93
  Bottom 0.203: v75.94,21.93 76.7,21.93 79.37,24.6 79.5,24.6 79.37,24.73 79.37,74.89 83.81,79.34 83.81,87.47 85.85,89.5 100.83,89.5 102.36,91.02 102.36,94.58 103.5,95.72 RS232.1
P2.5  (via drill 0.61)
  Top 0.203: v74.29,24.85 73.27,24.85 72.71,25.41 72.71,26.56 72.7,26.56 MSP1.59 | v82.93,85.56 R7.1
  Bottom 0.203: v74.29,24.85 77.21,24.85 78.35,26 78.35,75.65 82.93,80.23 v82.93,85.56 82.93,88.48 84.58,90.13 98.29,90.13 99.82,91.66 99.82,94.32 101.21,95.72 RS232.3
R03
  Top 0.254: MSP1.40 84.96,20.46 84.96,19.14 86.35,19.14 | 86.35,19.14 R4.2 | 86.35,19.14 87.62,19.14 87.62,20.92 89.02,20.92 | 89.02,20.92 R5.1 | 91.31,20.92 C9.2 89.02,20.92
R13
  Top 0.254: R4.1 86.35,21.04 | MSP1.41 R4.1 | R4.1 86.35,22.44 89.02,22.44 R3.2 91.18,24.29 91.18,24.35 C8.2
R23
  Top 0.254: MSP1.42 84.58,21.46 84.58,24.35 86.48,24.35 86.48,24.29 R2.2 87.62,24.29 87.62,26.12 89.02,26.12 | 89.02,26.12 R3.1 | 89.02,26.12 C7.2
R33
  Top 0.254: MSP1.43 84.07,21.96 84.07,26.12 86.35,26.12 R2.1 86.35,28.03 C6.2 91.31,28.03
RSTNMI  (via drill 0.61)
  Top 0.203: MSP1.58 73.21,39.27 72.13,40.35 | 70.48,49.4 70.48,77.69 v70.23,78.07
  Top 0.305: 72.13,40.35 71.75,40.22 71.75,40.09
  Top 0.406: 71.75,40.09 C5.1 | 68.88,40.04 R1.2 | 71.75,40.09 68.88,40.04 | S_B1.P$1 70.48,49.4 70.48,40.09 71.75,40.09 | 71.75,40.09 68.75,40.09 68.88,40.04
  Bottom 0.203: v70.23,78.07 77.34,78.07 78.35,79.08 78.35,85.05 76.19,87.21 72.64,87.21 71.11,88.73 71.11,94.45 SV1.11
S0
  Top 0.203: MSP1.12 66.74,18.96 65.27,17.49 65.27,9.11 70.1,4.28 96.13,4.28 106.93,15.08 106.93,20.28 114.04,27.39 114.04,69.05 112.64,70.45 110.87,70.45 110.79,70.52 LCD.P$27
S1
  Top 0.203: MSP1.13 67.01,18.46 65.78,17.23 65.78,9.23 70.1,4.92 96.01,4.92 106.42,15.33 106.42,20.41 113.53,27.52 113.53,67.14 112.26,68.41 110.87,68.41 110.76,68.52 LCD.P$28
S2  (via drill 0.61)
  Top 0.203: MSP1.14 67.14,17.96 66.29,17.11 66.29,9.61 70.48,5.42 95.75,5.42 105.91,15.58 105.91,20.79 113.02,27.9 113.02,65.62 v112.64,66
  Bottom 0.203: v112.64,66 112.64,73.24 111.37,74.51 LCD.P$25
S3  (via drill 0.61)
  Top 0.203: MSP1.15 67.28,17.46 66.8,16.98 66.8,10 70.86,5.93 95.5,5.93 104.52,14.95 v104.52,16.09 | LCD.P$23 86.1,69.22 86.1,64.1 88.39,61.81 88.39,54.32 89.78,52.92 104.13,52.92 105.53,51.52 v105.53,38.44
  Bottom 0.203: v105.53,38.44 104.52,37.43 v104.52,16.09
S4  (via drill 0.61)
  Top 0.203: MSP1.16 67.43,16.19 67.43,10.38 71.37,6.44 95.24,6.44 103.12,14.31 103.12,18.63 112.39,27.9 112.39,63.08 v111.88,63.59
  Bottom 0.203: v111.88,63.59 111.75,63.72 111.75,71.72 110.99,72.48 110.74,72.48 LCD.P$26
S5  (via drill 0.61)
  Top 0.203: MSP1.17 70.21,14.17 v69.59,13.55 | v102.86,39.08 104.01,40.22 104.01,50.63 v103.25,51.4
  Bottom 0.203: v69.59,13.55 69.59,8.22 71.37,6.44 95.12,6.44 102.86,14.19 v102.86,39.08 | v103.25,51.4 103.25,51.52 102.99,51.78 91.44,51.78 88.26,54.95 88.26,73.88 87.62,74.51 84.58,74.51 LCD.P$24
S6  (via drill 0.61)
  Top 0.203: v96.74,9.59 79.7,9.59 78.07,7.96 75.2,7.96 74.77,8.39 72.87,8.39 70.5,10.76 70.15,10.76 69.59,11.32 69.59,12.03 70.71,13.15 70.71,14.21 MSP1.18 | v101.9,41.92 101.49,42.46 101.49,49.42 v100.66,50.25
  Bottom 0.203: v96.74,9.59 97.91,10.76 97.91,11.34 99.56,12.99 99.56,13.58 100.78,14.8 100.78,18.88 101.19,19.29 101.19,21.07 98.88,23.38 98.88,37.15 101.85,40.12 101.85,41.87 v101.9,41.92 | v100.66,50.25 91.61,50.25 87.4,54.47 87.4,61 84.14,64.25 84.14,65.62 83.74,66.03 83.74,67.45 83.16,68.03 LCD.P$21
S7  (via drill 0.61)
  Top 0.203: v91.18,7.53 75.05,7.53 74.62,7.96 72.71,7.96 70.35,10.33 70,10.33 68.78,11.54 68.78,15.2 69.64,16.07 71.17,16.07 71.22,16.02 71.22,15.71 MSP1.19 | v97.66,23.43 v94.81,26.28 | v92.09,39.1 v93.72,40.73 | v94.08,43.22 92.93,43.22 92.22,43.93 v92.22,44.51
  Bottom 0.203: v91.18,7.53 95.32,11.67 97.07,11.67 98.75,13.35 98.75,13.93 99.97,15.15 99.97,19.24 100.38,19.65 100.38,20.71 v97.66,23.43 | v94.81,26.28 95.22,26.68 95.22,33.41 92.12,36.51 92.12,39.08 v92.09,39.1 | v93.72,40.73 93.72,41.69 94.08,42.05 v94.08,43.22 | v92.22,44.51 91.33,45.4 90.75,45.4 89.83,46.32 89.83,50.86 86.58,54.12 86.58,60.64 83.18,64.05 LCD.P$19
S8  (via drill 0.61)
  Top 0.203: v101.59,18.53 101.01,18.53 98.06,15.58 98.06,14.42 96.19,12.54 93.85,12.54 92.17,10.86 88.39,10.86 88.03,10.5 79.45,10.5 77.77,8.83 75.51,8.83 75.08,9.26 74.44,9.26 73.22,10.48 71.95,10.48 71.34,11.09 71.34,12.51 71.7,12.87 71.7,14.21 MSP1.20 | v102.76,42.91 101.9,43.52 v101.9,50.18
  Bottom 0.203: v101.59,18.53 101.59,21.25 99.28,23.56 99.28,36.77 102.74,40.22 102.76,40.35 v102.76,42.91 | v101.9,50.18 100.98,51.09 91.36,51.09 87.8,54.65 87.8,61.18 84.55,64.43 84.55,65.8 84.14,66.2 84.14,67.63 83.74,68.03 83.74,69.46 83.16,70.04 LCD.P$22
S9  (via drill 0.61)
  Top 0.203: v71.98,16.42 72.13,16.42 72.21,16.34 72.21,15.71 MSP1.21 | v70.4,11.67 70.81,11.27 70.81,11.04 73.02,8.83 74.92,8.83 75.36,8.39 77.92,8.39 79.6,10.07 88.18,10.07 88.54,10.43 v95.83,10.43 | v100.88,41.13 100.88,40.96 100.83,41.41 100.83,48.27 100.66,48.45 v100.66,49.03
  Bottom 0.203: v71.98,16.42 72.66,15.74 72.66,13.93 v70.4,11.67 | v95.83,10.43 97,10.43 97.51,10.94 97.51,11.52 99.16,13.17 99.16,13.75 100.38,14.97 100.38,19.06 100.78,19.47 100.78,20.89 98.47,23.2 98.47,37.48 100.83,39.84 100.83,41.11 100.86,41.11 v100.88,41.13 | v100.66,49.03 92.25,49.03 86.99,54.29 86.99,60.82 83.74,64.07 83.74,65.44 83.16,66.03 LCD.P$20
S10  (via drill 0.61)
  Top 0.203: v77.52,10.91 72.11,10.91 71.75,11.27 71.75,12.33 72.71,13.3 72.71,14.21 MSP1.22 | v84.55,58.64 83.16,60.03 LCD.P$17
  Bottom 0.203: v77.52,10.91 92.22,10.91 93.67,12.36 93.67,12.94 96.21,15.48 96.79,15.48 97.53,16.22 97.53,18.43 95.22,20.74 95.22,21.73 94.74,22.21 92.6,22.21 89.43,25.39 89.43,38.19 88.62,39 88.62,50.33 84.55,54.39 v84.55,58.64
S11  (via drill 0.61)
  Top 0.203: v72.31,17.95 73.2,17.08 73.2,15.71 MSP1.23 | v98.67,20.21 v95.22,23.66 | v93.21,42.35 v91,44.56 | v85.77,54.93 84.7,54.93 83.38,56.25 LCD.P$15
  Bottom 0.203: v72.31,17.95 73.2,17.06 73.2,13.88 72.77,13.45 72.77,11.52 73.96,10.33 73.96,9.74 74.44,9.26 91.74,9.26 95.02,12.54 96.77,12.54 97.94,13.7 97.94,14.29 99.16,15.51 99.16,19.14 98.67,19.62 v98.67,20.21 | v95.22,23.66 95.63,24.07 95.63,33.59 92.91,36.31 92.91,42.05 v93.21,42.35 | v91,44.56 89.43,46.14 89.43,50.69 85.77,54.34 v85.77,54.93
S12  (via drill 0.61)
  Top 0.203: MSP1.24 73.71,17.74 v73.78,17.74 | v104.39,39.2 105.02,39.97 105.02,51.27 103.88,52.41 89.28,52.41 87.88,53.81 87.88,61.68 87.04,62.52 LCD.P$18
  Bottom 0.203: v73.78,17.74 72.77,18.76 71.88,18.76 70.99,17.87 70.99,16.34 69.34,14.69 68.7,14.69 68.07,14.06 68.07,8.6 70.99,5.68 95.24,5.68 103.5,13.93 103.5,38.19 v104.39,39.2
S13  (via drill 0.61)
  Top 0.203: v73.98,12.92 73.98,13.5 74.21,13.73 74.21,14.21 MSP1.25 | v85.36,56.27 83.38,58.25 LCD.P$16
  Bottom 0.203: v73.98,12.92 74.01,12.89 75.53,12.89 76.7,11.72 76.7,10.55 77.19,10.07 91.97,10.07 94.08,12.18 94.08,12.76 96.36,15.05 96.95,15.05 97.94,16.04 97.94,18.61 95.63,20.92 95.63,21.91 94.89,22.64 92.76,22.64 89.83,25.56 89.83,38.37 89.02,39.18 89.02,50.51 84.96,54.57 84.96,55.87 v85.36,56.27
S14  (via drill 0.61)
  Top 0.203: v75.53,11.72 75.53,12.31 74.8,13.04 74.8,13.27 74.7,13.37 74.7,14.21 MSP1.26 | v75.99,10.1 76.58,10.1 76.96,9.72 77.49,9.72 79.14,11.37 87.73,11.37 90.32,13.96 90.9,13.96 91.99,15.05 v92.86,15.05 | v87.4,46.16 86.53,46.16 84.55,48.15 84.55,50.63 83.16,52.03 LCD.P$13
  Bottom 0.203: v75.53,11.72 75.53,10.55 v75.99,10.1 | v92.86,15.05 93.44,15.05 94.28,15.89 94.28,17.51 88.56,23.23 88.56,24.5 88.21,24.85 88.21,37.66 87.4,38.47 87.4,41.29 86.58,42.1 86.58,44.28 86.99,44.69 86.99,45.76 v87.4,46.16
S15  (via drill 0.61)
  Top 0.203: v90.8,15.08 88.67,15.08 87.14,13.55 83.2,13.55 81.45,11.8 76.63,11.8 75.2,13.22 75.2,14.21 MSP1.27 | v93.47,17.16 94.41,18.1 v94.41,21.27 | v87.8,43.73 83.33,48.2 LCD.P$11
  Bottom 0.203: v90.8,15.08 91.64,15.91 92.22,15.91 v93.47,17.16 | v94.41,21.27 92.96,21.27 89.02,25.21 89.02,38.01 88.21,38.82 88.21,43.32 v87.8,43.73
S16  (via drill 0.61)
  Top 0.203: v81.1,12.64 76.37,12.64 75.71,13.3 75.71,14.21 MSP1.28
  Bottom 0.203: v81.1,12.64 82.21,12.64 83.41,13.83 83.41,15 85.92,17.51 85.92,18.1 86.99,19.16 86.99,37.12 86.18,37.94 86.18,40.75 84.55,42.38 84.55,43.09 86.02,44.56 86.28,44.56 86.58,44.87 86.58,51.19 83.51,54.27 83.38,54.27 LCD.P$14
S17  (via drill 0.61)
  Top 0.203: v74.72,16.42 75.58,16.42 76.19,15.81 76.19,15.71 MSP1.29 | v74.77,10.1 74.82,10.1 75.66,9.26 77.62,9.26 79.29,10.94 87.88,10.94 88.23,11.29 92.02,11.29 92.86,12.13 v92.86,12.71 | v87.8,44.95 87.17,44.95 84.14,47.97 84.14,49.49 83.38,50.25 LCD.P$12
  Bottom 0.203: v74.72,16.42 74.72,14.82 73.17,13.27 73.17,11.7 v74.77,10.1 | v92.86,12.71 95.91,15.76 95.91,17.06 95.17,17.79 94.58,17.79 88.97,23.41 88.97,24.68 88.62,25.03 88.62,37.83 87.8,38.65 87.8,41.47 86.99,42.28 86.99,44.11 87.8,44.92 v87.8,44.95
S18  (via drill 0.61)
  Top 0.203: v76.75,13.45 76.7,13.5 76.7,14.21 MSP1.30 | v91.69,12.13 91.69,12.71 92.53,13.55 95.68,13.55 v95.85,13.37 | v97.73,38.93 97.73,39.51 99.05,40.83 99.05,43.17 99.46,43.57 99.46,44.64 98.32,45.78 91.03,45.78 88.13,42.89 87.19,42.89 85.82,44.26 83.38,44.26 LCD.P$9
  Bottom 0.203: v76.75,13.45 78.81,11.39 90.95,11.39 v91.69,12.13 | v95.85,13.37 97.02,13.37 97.53,13.88 97.53,14.46 98.75,15.69 98.75,18.96 96.44,21.27 96.44,37.05 97.73,38.34 v97.73,38.93
S19  (via drill 0.61)
  Top 0.203: v76.75,16.42 77.13,16.42 77.21,16.34 77.21,15.71 MSP1.31
  Bottom 0.203: v76.75,16.42 76.75,16.8 77.64,17.69 83.43,17.69 83.56,17.56 84.22,17.56 84.7,18.05 84.7,18.63 85.77,19.7 85.77,36.59 84.55,37.81 84.58,37.81 84.58,38.75 LCD.P$7
S20  (via drill 0.61)
  Top 0.203: v81.94,13.53 77.72,13.53 77.69,13.55 77.69,14.21 MSP1.32
  Bottom 0.203: v81.94,13.53 81.94,14.11 85.52,17.69 85.52,18.27 86.58,19.34 86.58,36.94 85.77,37.76 85.77,40.58 84.14,42.2 84.14,43.62 83.74,44.03 83.74,45.45 83.16,46.04 LCD.P$10
S21  (via drill 0.61)
  Top 0.203: v83.31,16.65 83,16.95 80.44,16.95 MSP1.33
  Bottom 0.203: v83.31,16.65 83.79,17.13 84.37,17.13 85.11,17.87 85.11,18.45 86.18,19.52 86.18,36.77 85.36,37.58 85.36,40.17 84.81,40.73 84.45,40.73 83.16,42.02 LCD.P$8
S22  (via drill 0.61)
  Top 0.203: v86.81,16.55 84.93,16.55 84.02,17.46 80.44,17.46 MSP1.34 | v85.77,43.14 85.36,43.55 81.55,43.55 v81.33,43.45
  Bottom 0.203: v86.81,16.55 86.81,16.65 87.57,17.41 87.57,23.74 88.16,24.32 87.8,24.68 87.8,37.48 86.99,38.29 86.99,41.11 86.18,41.92 86.18,43.09 86.13,43.14 v85.77,43.14 | LCD.P$5 82.8,36.54 81.33,38.01 v81.33,43.45
S23  (via drill 0.61)
  Top 0.203: v82.95,19.62 82.06,18.73 81.88,18.73 81.12,17.97 80.44,17.97 MSP1.35
  Bottom 0.203: v82.95,19.62 82.95,21.83 84.96,23.84 84.96,31.94 84.42,32.47 82.8,32.47 LCD.P$3
S24  (via drill 0.61)
  Top 0.203: v78.23,21.91 78.23,22.39 78.3,22.47 78.96,22.47 MSP1.44 | v83.56,18.5 84.3,17.77 v86.76,17.77 | v90.65,13.12 91.77,14.24 v96.72,14.24 | v96.57,38.34 96.57,38.93 98.65,41.01 98.65,43.34 99.05,43.75 99.05,44.46 98.57,44.95 97.38,44.95 | 97.38,44.95 v94.05,44.95 | v108.43,75.93 110.81,78.32 SV2.1 | 97.38,44.95 v97.38,44.97 | LCD.P$6 82.8,38.57 84.96,40.73 v89.83,40.73
  Bottom 0.203: v78.23,21.91 81.63,18.5 v83.56,18.5 | v86.76,17.77 86,17 86,14.03 86.91,13.12 v90.65,13.12 | v96.72,14.24 98.34,15.86 98.34,18.78 96.03,21.09 96.03,37.81 v96.57,38.34 | v94.05,44.95 v89.83,40.73 | v108.43,75.93 108.83,75.53 108.83,54.7 99.11,44.97 v97.38,44.97
S25  (via drill 0.61)
  Top 0.203: v81.73,22.95 80.44,22.95 MSP1.45 | v108.83,78.88 110.81,80.86 SV2.2 | v98.24,44.11 98.24,41.19 v95.35,38.29 | LCD.P$4 82.8,34.89 84.58,36.66 v93.72,36.66
  Bottom 0.203: v81.73,22.95 79.78,24.9 79.78,34.02 80.64,34.89 82.42,34.89 82.8,34.51 LCD.P$4 | v108.83,78.88 109.24,78.47 109.24,54.52 98.83,44.11 v98.24,44.11 | v93.72,36.66 v95.35,38.29
S26  (via drill 0.61)
  Top 0.203: MSP1.46 80.44,23.46 81.07,23.46 82.55,24.93 82.55,27.93 LCD.P$1 83.38,28.26 84.98,28.26 89,32.27 v97.66,32.27 | v108.07,50.63 108.07,72.35 107.44,72.99 107.44,81.24 110.36,84.16 SV2.3
  Bottom 0.203: v97.66,32.27 98.04,32.65 98.04,37.94 99.82,39.71 99.82,42.38 v108.07,50.63
S27  (via drill 0.61)
  Top 0.203: v80.59,26.58 80,26.58 78.48,25.06 78.48,23.96 78.96,23.96 MSP1.47 | v81.02,33.9 81.43,34.3 81.43,37.02 81.83,37.43 81.83,37.45 81.86,37.48 v107.69,37.48 | SV2.4 111.63,86.7 106.67,81.75 106.67,47.97 107.56,47.08 v107.69,47.08
  Bottom 0.203: v80.59,26.58 80.18,26.99 80.18,33.64 80.44,33.9 v81.02,33.9 | LCD.P$43 110.54,38.27 109.88,37.48 v107.69,37.48 v107.69,47.08
S28  (via drill 0.61)
  Top 0.203: MSP1.48 80.44,24.45 81.48,24.45 82.14,25.11 82.14,27.27 81.83,27.57 81.83,29.48 82.42,30.06 LCD.P$2 83.38,30.8 84.17,30.8 87.3,33.92 v90.65,33.92 | v108.83,86.5 110.81,88.48 SV2.5
  Bottom 0.203: v108.83,86.5 108.83,80.63 107.44,79.23 107.44,72.91 | 107.44,72.91 108.43,71.92 108.43,54.88 99.36,45.81 96.08,45.81 94.38,44.11 93.8,44.11 90.65,40.96 90.65,35.34 90.62,34.81 90.62,34.2 v90.65,33.92 | 107.44,72.91 107.44,72.86
S29  (via drill 0.61)
  Top 0.203: v81.02,29.55 79.01,29.55 77.69,28.23 77.69,27.19 MSP1.49 | v83.71,29.55 84.45,30.29 84.45,30.49 87.04,33.08 107.41,33.08 110.59,36.26 110.66,36.39 LCD.P$44 | v111.83,75.91 110.36,75.91 109.67,75.22 v109.67,41.64
  Bottom 0.203: v81.02,29.55 v83.71,29.55 | v109.67,41.64 109.75,41.57 111.53,41.57 111.86,41.24 111.86,37.2 111.32,36.54 LCD.P$44 | v111.83,75.91 111.83,75.86 111.93,75.86 109.7,78.09 109.65,78.22 109.65,84.8 110.05,85.2 110.05,89.95 SV2.6
S30  (via drill 0.61)
  Top 0.203: v73.48,23.94 74.54,23.94 75.15,24.55 76.7,24.55 77.21,25.06 77.21,25.72 MSP1.50 | v77.01,29.3 76.6,29.7 76.6,38.11 80.03,41.54 v97.43,41.54
  Bottom 0.203: v73.48,23.94 73.07,24.35 73.07,25.95 76.42,29.3 v77.01,29.3 | v97.43,41.54 110.16,54.27 LCD.P$35 111.32,54.8 114.02,57.49 114.02,92.49 112.95,93.56 SV2.7
S31  (via drill 0.61)
  Top 0.203: v84.96,35.55 107.03,35.55 109.21,37.73 109.21,39.08 110.61,40.48 110.74,40.48 | MSP1.51 76.7,27.19 76.7,27.83 78.99,30.11 78.99,30.7 79.88,31.58 84.2,31.58 84.96,32.35 v84.96,33.49 | 111.75,50.52 111.75,52.52 | 111.75,52.52 111.75,52.54 110.74,52.54 LCD.P$36 111.75,52.52 | 111.75,52.52 111.75,55.59 110.74,56.6 LCD.P$34 LCD.P$33 LCD.P$32 | LCD.P$32 110.74,60.54 | 110.82,62.52 110.87,62.57 | 110.82,62.52 LCD.P$31 LCD.P$30 | LCD.P$32 110.74,62.45 110.82,62.52 | LCD.P$30 110.74,64.61 | LCD.P$30 LCD.P$29 | 110.74,42.51 LCD.P$42 110.74,40.48 | 111.75,50.52 LCD.P$37 | 111.75,50.52 111.75,45.55 110.74,44.54 LCD.P$40 110.74,42.51 | 110.74,42.51 LCD.P$41 | SV2.8 105.53,90.51 105.53,52.54 106.04,52.03 106.04,42 107.56,40.48 110.74,40.48
  Bottom 0.203: v84.96,33.49 v84.96,35.55
TCK
  Top 0.203: MSP1.57 73.71,26.77 73.71,42.07 73.15,42.63 73.15,84.54 74.54,85.94 75.81,85.94 76.19,86.58 76.19,94.45 SV1.7
TDI
  Top 0.203: MSP1.55 74.67,27.14 74.67,83.02 75.69,84.04 78.73,84.04 81.27,86.58 81.27,94.45 SV1.3
TDO
  Top 0.203: MSP1.54 75.18,81.88 76.58,83.27 79.12,83.27 84.07,88.23 84.07,94.2 SV1.1
TMS
  Top 0.203: MSP1.56 74.16,27.14 74.16,83.53 75.31,84.67 77.85,84.67 78.73,85.56 78.73,94.45 SV1.5
U+
  Top 0.406: IC3.1 43.87,66.45 43.94,66.38 44.06,66.51 | 43.94,66.51 43.94,66.45 IC3.1 | IC3.1 43.85,65.53 42.79,64.48 | 47.37,73.37 R30.1 | 47.37,73.37 44.39,73.37 C19.2 44.32,73.37 39.82,73.37 39.82,72.94 C17.2 | IC3.1 46.54,66.45 47.37,67.27 47.37,73.37
  Top 0.813: 42.79,64.48 42.29,63.97 22.73,63.97 20.82,62.06 20.82,55.97 20.82,54.95 20.95,54.83 20.93,54.8 D7.2
V1+  (via drill 0.61)
  Top 0.203: MSP1.6 54,21.96 v53.21,21.17 | C23.1 17.04,33.59 17.22,33.59
  Top 0.254: 17.22,35.06 17.27,35.14 19.68,37.55 v46.1,37.55
  Top 0.406: 17.22,35.01 17.22,35.06 | R42.2 17.22,33.59 17.22,35.01 | 17.22,35.01 17.39,35.01
  Bottom 0.254: v53.21,21.17 53.21,36.03 51.81,37.43 46.35,37.43 v46.1,37.55
V1-
  Top 0.203: MSP1.7 68.21,21.44 68.19,21.42 55.11,21.42
  Top 0.254: 24.25,21.81 C26.1 | R24.2 22.98,21.81 24.25,21.81 | 55.11,21.42 51.3,17.61 51.18,17.36 51.18,3.26 49.53,1.61 23.24,1.61 20.7,4.15 20.7,14.44 21.97,15.71 23.49,15.71 24.51,16.73 24.51,21.55 24.25,21.81
VCC  (via drill 0.61)
  Top 0.203: 67.96,24.57 MSP1.1 | 67.38,24.85 68.19,24.47 | 78.86,97.24 78.86,95.21 79.88,94.2 79.88,93.18 SV1.4 | R7.2 87.3,83.91 88.26,83.91
  Top 0.254: R22.2 R21.2 19.76,86.75 20.44,86.07 24.12,86.07 25.01,87.08 29.97,87.08 30.35,86.7 30.35,85.56 | 30.35,83.02 30.35,85.56 | 30.35,85.56 D1.2
  Top 0.305: 68.19,24.47 67.96,24.57 | 66.11,26.12 C1.1 | Q3.E 61.7,86.07 71.5,86.07 73.78,88.35 73.78,96.48 74.54,97.24 78.86,97.24
  Top 0.406: SV3.2 28.82,80.73 28.7,80.86 | 66.29,38.11 R1.1 | 66.42,35.01 R29.1 66.16,35.01 | 65.4,35.01 66.16,35.01 | 66.29,36.28 66.29,35.01 66.16,35.01 | v49.78,83.02 50.16,83.02 v50.16,79.21 | 78.86,97.24 90.8,97.24 91.82,96.23 91.82,93.31 93.34,93.31 RS232.10
  Top 0.61: 62.02,31.28 61.97,31.23 61.97,31.2 C2.+ 62.1,31.13 | v81.53,83.91 88.26,83.91 91.82,87.47 91.82,93.31
  Top 0.813: C1.1 67.38,24.85 | 62.1,31.13 62.1,27.52 63.5,26.12 66.11,26.12 | 28.7,83.02 28.7,80.86 | 30.35,83.02 30.7,83.02
  Top 1.93: 28.7,83.02 30.35,83.02 v49.78,83.02 60.07,83.02 v66.29,76.8 66.29,38.11 66.29,36.28 | 62.02,31.28 61.97,31.33 61.97,33.87 63.11,35.01 65.4,35.01
  Bottom 0.254: LED2.A 41.78,89.62 49.78,89.62 LED1.A v49.78,83.02
  Bottom 0.61: v66.29,76.8 77.97,76.8 81.53,79.97 v81.53,83.91
VCC1
  Top 0.406: J1.VCC2 13.84,67.02 D2.1
VCC2
  Top 0.406: 21.04,73.66 21.08,73.62 | 21.04,73.66 IC2.5 21.04,70.74 21.08,70.7 C14.2 | 21.04,73.66 20.82,73.88 16.76,73.88 16.76,75.02 16.63,75.02 | 16.63,79.08 16.76,79.08
  Top 0.813: 16.76,79.08 18.28,80.35 SV3.3 | 16.63,77.18 16.63,79.08 | 16.63,77.18 C12.+ | 16.63,75.02 16.63,77.18
VCC_PL  (via drill 0.61)
  Top 0.406: 37.64,66.76 37.97,66.76 37.97,66.51 C21.2 | 47.11,78.7 ZD1.2 | R30.2 47.11,75.32 47.11,78.7 | 47.11,78.7 47.11,79.46 46.1,80.48 31.11,80.48 SV3.1
  Top 0.813: IC3.5 38.03,66.45 37.97,66.51 | 37.64,66.76 35.17,66.76 v35.3,66.64 35.3,72.86 35.43,72.86 C16.+
  Bottom 0.813: SV3.1 33.52,80.35 35.3,78.58 v35.3,66.64
VREF(I)
  Top 0.203: TP3.1 53.46,8.85 56.76,8.85 | MSP1.10 66.6,19.96 64.64,18 64.64,8.34 63.62,7.33 58.29,7.33 56.76,8.85 | 56.76,8.85 C29.2
XIN
  Top 0.203: MSP1.8 64.55,20.96 63.83,20.97 61.97,19.11 Q1.2
XOUT
  Top 0.203: MSP1.9 65.58,20.46 Q1.1

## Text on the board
Top: MSP430FE42XX Ref. Board | Ver: 2.4
Descript: TP2 | TP1 | LED2 | LED1 | LED3 | RS232 | S_B | S_A | JTAG | J1 | Vcc | GND | P1.0 - P1.7 | GND | Vin | V1 | I1 | I2 | TP3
